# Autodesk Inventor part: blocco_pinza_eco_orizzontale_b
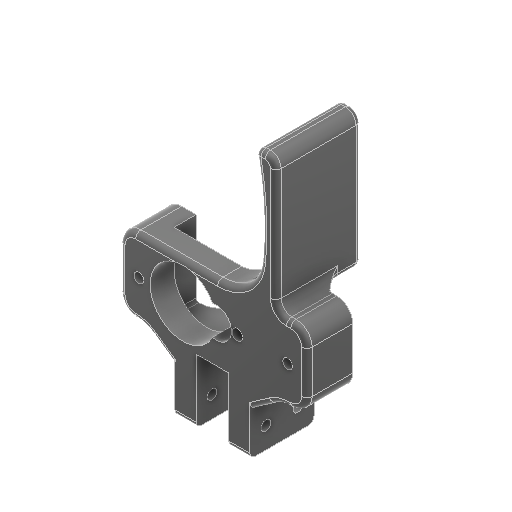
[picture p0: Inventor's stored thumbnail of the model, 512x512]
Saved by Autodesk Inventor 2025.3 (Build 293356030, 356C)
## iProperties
Created: 2026-03
Part Number: blocco_pinza_eco_orizzontale_b
Material: Plastica ABS
Document SubType Name: Modeling
Designer: Ryzen5700u
Density: 1.06 g/cm^3
Appearance: Liscia - Nero
Author: Ryzen5700u
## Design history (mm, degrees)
sketch "Schizzo1"
  geometry: L1 (11.4, -6)-(11.4, 6) reference; L2 (17.5, -7)-(-17.5, -7); L3 (-17.5, -7)-(-17.5, 7); L4 (-17.5, 7)-(17.5, 7); L5 (17.5, 7)-(17.5, -7); A1 r 2.7 centre (0.55, 0) between (-0.234, -2.584) and (-0.234, 2.584) reference; A2 r 6 centre (-5.65, 0) between (-0.234, 2.584) and (-0.234, -2.584) reference; A3 r 2.85 centre (0.55, 0) between (-0.155, -2.762) and (-0.155, 2.762); A4 r 6.15 centre (-5.65, 0) between (-0.155, 2.762) and (-0.155, -2.762); 1 further point
  constraints: 8 end point, 8 point on circle, 4 centre point, 2 parallel, 1 horizontal, 1 perpendicular, 7 other
  dimensions: "d1" = 35 distance of L3.end L4.end; "d2" = 14 distance of L2.end L3.end; "d66" = 0.15 radial gap between concentric circles of A2 A4
extrude "Estrusione1" new body sketch "Schizzo1" distance "d4" = 4.5; taper "d5" = 0 deg
sketch "Schizzo3"
  geometry: L1 (-17.5, 7)-(17.5, 7) reference; L2 (-17.5, -7)-(-17.5, 7) reference; L3 (17.5, -7)-(-17.5, -7) reference; L4 (17.5, 7)-(17.5, -7) reference; L5 (-11.7, 7)-(-11.7, -7); L6 (11.8, 7)-(11.8, -7); 1 further point
  constraints: 4 end point, 4 point on line, 2 perpendicular
  dimensions: "d13" = 5.8 distance between parallel lines of L2 L5; "d14" = 5.7 distance between parallel lines of L4 L6
  node "Linea chiusa proiettata1"
node "Piano di lavoro1"
extrude "Estrusione2" join sketch "Schizzo3" distance "d15" = 4.1; taper "d16" = 0 deg
fillet "Raccordo1" dims "d17" = 3
sketch "Schizzo4"
  geometry: L1 (11, -7)-(11, 33); L2 (17.5, -4)-(17.5, 4) reference; L3 (7, -7)-(7, 33); L4 (11, 33)-(7, 33); L5 (-14.5, -7)-(14.5, -7) reference; 1 further point
  constraints: 6 end point, 1 horizontal, 1 parallel, 1 point on line, 1 vertical
  dimensions: "d18" = 40 distance of L1.start L1.end; "d19" = 6.5 distance between parallel lines of L2 L1; "d20" = 4 distance between parallel lines of L1 L3
extrude "Estrusione3" join sketch "Schizzo4" distance "d21" = 10; taper "d22" = 0 deg
chamfer "Smusso1" distance "d23" = 5; stored, may be unused: second distance "d24" = 2, angle "d25" = 45 deg
chamfer "Smusso2" distance "d26" = 5; stored, may be unused: second distance "d27" = 2, angle "d28" = 45 deg
sketch "Schizzo5"
  geometry: L1 (11.8, 0)-(11.65, -25.421) reference; L2 (14.65, 4.5)-(8.65, 4.5); L3 (8.65, 4.5)-(8.65, -7.5); L4 (8.65, -7.5)-(14.65, -7.5); L5 (14.65, -7.5)-(14.65, 4.5); L6 (14.65, 4.5)-(18.65, 4.5); L7 (18.65, 4.5)-(18.65, -7.5); L8 (18.65, -7.5)-(14.65, -7.5); L9 (14.65, -7.5)-(14.65, 4.5); L10 (8.65, 4.5)-(4.65, 4.5); L11 (4.65, 4.5)-(4.65, -7.5); L12 (4.65, -7.5)-(8.65, -7.5); L13 (8.65, -7.5)-(8.65, 4.5); 4 further points
  constraints: 26 end point, 6 parallel, 3 horizontal, 3 perpendicular, 3 point on line, 2 vertical, 1 other
  dimensions: "d29" = 6 distance of L4.end L3.end; "d30" = 12 distance of L3.end L2.end; "d31" = 4 distance of L7.end L8.end; "d32" = 4 distance of L12.end L11.end
extrude "Estrusione4" join sketch "Schizzo5" distance "d33" = 12; taper "d34" = 0 deg
sketch "Schizzo6"
  geometry: C1 r 2.45 at (6, -6) reference; 1 further point
hole "Foro2" sketch "Schizzo6" at (6, -6) diameter "d41" = 3.2; stored, may be unused: countersink angle "d45" = 90 deg, drill point angle "d47" = 118 deg; dims "d42" = 6, "d43" = 6.5, "d44" = 3.4, "d46" = 8
chamfer "Smusso5" distance "d48" = 2.7; stored, may be unused: second distance "d49" = 2, angle "d50" = 45 deg
fillet "Raccordo2" dims "d51" = 3
sketch "Schizzo7"
  geometry: L1 (0, 4.5)-(0, 0) reference; L2 (0, 0)-(6, 0) reference; L3 (6, 0)-(6, 4.5) reference; L4 (0, 4.5)-(6, 4.5) reference; 1 further point
extrude "Estrusione5" join sketch "Schizzo7" stored distance "d52" = 10; taper "d53" = 0 deg
sketch "Schizzo8"
  geometry: L1 (-7.15, -19)-(-3.15, -19) reference; L2 (-7.15, -19)-(6.85, -19); L3 (6.85, -19)-(6.85, -14); L4 (6.85, -14)-(-7.15, -14); L5 (-7.15, -14)-(-7.15, -19); 7 further points
  constraints: 8 end point, 2 parallel, 1 horizontal, 1 perpendicular, 2 other
  dimensions: "d63" = 5 distance of L3.end L2.end
extrude "Estrusione6" cut sketch "Schizzo8" distance "d64" = 15; taper "d65" = 0 deg
sketch "Schizzo10"
  geometry: A1 r 1 centre (13.9, 0) between (14.7, 0.6) and (14.7, -0.6) reference; A2 r 1 centre (-13.9, 0) between (-14.7, -0.6) and (-14.7, 0.6) reference; 1 further point
  constraints: 4 point on circle, 2 centre point, 8 other
hole "Foro3" sketch "Schizzo10" at (13.9, 0), (-13.9, 0) diameter "d67" = 1.8; stored, may be unused: countersink angle "d71" = 90 deg, drill point angle "d73" = 118 deg; dims "d68" = 6, "d69" = 3.5, "d70" = 1.8, "d72" = 8
chamfer "Smusso9" distance "d74" = 4; stored, may be unused: second distance "d75" = 2, angle "d76" = 45 deg
sketch "Schizzo11"
  geometry: L1 (10, 5)-(1.15, -3.85) reference; L2 (10, 40)-(10, 5) reference; L3 (0, 40)-(10, 40) reference; L4 (0, 40)-(0, 14) reference; L5 (0, -3.85)-(0, 14) reference; L6 (0, -3.85)-(1.15, -3.85) reference; 1 further point
extrude "Estrusione7" cut sketch "Schizzo11" extent not by distance; stored distance "d77" = 0; taper "d78" = 0 deg
fillet "Raccordo3" dims "d79" = 1
sketch "Schizzo12"
  geometry: C1 r 1 at (4.5, 0) reference; 1 further point
hole "Foro4" sketch "Schizzo12" at (4.5, 0) diameter "d80" = 2; stored, may be unused: countersink angle "d84" = 90 deg, drill point angle "d86" = 118 deg; dims "d81" = 6, "d82" = 3.5, "d83" = 1.8, "d85" = 8
sketch "Schizzo13"
  geometry: L1 (4, -11)-(0, -11) reference; L2 (4, 0)-(4, -11) reference; L3 (4, 0)-(0, 0) reference; L4 (0, 0)-(0, -11) reference; L5 (14, -11)-(10, -11) reference; L6 (14, 0)-(14, -11) reference; L7 (14, 0)-(10, 0) reference; L8 (10, 0)-(10, -11) reference; L9 (10, 0)-(4, 0) reference; L10 (3.95, 14.018)-(10.05, 14.018); L11 (10.05, 14.018)-(10.05, -14.018); L12 (10.05, -14.018)-(3.95, -14.018); L13 (3.95, -14.018)-(3.95, 14.018); L14 (3.95, 14.018)-(10.05, -14.018); L15 (10.05, 14.018)-(3.95, -14.018); 6 further points
  constraints: 12 end point, 3 midpoint, 2 parallel, 1 horizontal, 1 perpendicular
  dimensions: "d87" = 6.1 distance of L11.end L12.end
extrude "Estrusione8" cut sketch "Schizzo13" extent not by distance; stored distance "d88" = 0; taper "d89" = 0 deg
sketch "Schizzo15"
  geometry: L1 (11.7, 7)-(11.7, -7) reference; L2 (11.7, 7)-(7.7, 7); L3 (7.7, 7)-(7.7, 32); L4 (7.7, 32)-(11.7, 32); L5 (11.7, 32)-(11.7, 7); L6 (11.7, 7)-(-11.8, 7) reference; L7 (7.7, 7)-(11.7, 7); L8 (11.7, 7)-(11.7, 6.8); L9 (11.7, 6.8)-(7.7, 6.8); L10 (7.7, 6.8)-(7.7, 7); 2 further points
  constraints: 16 end point, 4 parallel, 2 horizontal, 2 perpendicular, 1 point on line
  dimensions: "d90" = 4 distance of L3.end L4.end; "d91" = 25 distance of L2.end L3.end; "d94" = 0.2 distance of L7.end L8.end
extrude "Estrusione9" join sketch "Schizzo15" distance "d92" = 16; taper "d93" = 0 deg
fillet "Raccordo4" dims "d95" = 2
sketch "Schizzo16"
  geometry: L1 (-11.7, 32)-(-7.7, 32) reference; L2 (-7.7, 32)-(-7.7, 7) reference; A1 r 60 centre (50.983, 19.5) between (-7.7, 32) and (-7.7, 7); 1 further point
  constraints: 2 point on circle, 1 centre point
  dimensions: "d96" = 60 radius of A1
extrude "Estrusione10" cut sketch "Schizzo16" extent not by distance; stored distance "d97" = 0; taper "d98" = 0 deg
fillet "Raccordo5" dims "d99" = 2
fillet "Raccordo6" dims "d100" = 1
fillet "Raccordo7" dims "d101" = 3
fillet "Raccordo8" dims "d102" = 1
fillet "Raccordo9" dims "d103" = 8
fillet "Raccordo10" dims "d104" = 5
sketch "Schizzo17"
  geometry: L1 (0, 0)-(0, 6.922) reference; L2 (0, 0)-(0, -0.155) reference; L3 (0, -7.078)-(0, -0.155) reference; L4 (4.1, 6.922)-(4.1, -7.078) reference; L5 (0, 6.922)-(4.1, 6.922) reference; L6 (0, 6.022)-(0, -6.178) reference; L7 (4.1, -7.078)-(-4.5, -7.078) reference; L8 (0, -7.078)-(4.1, -7.078); L9 (0, -7.078)-(4.1, -7.078) reference; L10 (0, 6.022)-(3.8, 6.022) reference; L11 (3.8, 6.022)-(3.8, -6.178) reference; L12 (3.8, -6.178)-(0, -6.178) reference; 6 further points
  constraints: 2 end point, 2 point on line, 1 collinear
extrude "Estrusione11" join sketch "Schizzo17" stored distance "d105" = 10; taper "d106" = 0 deg
sketch "Schizzo18"
  geometry: L1 (7.15, -11)-(7.15, -7) reference; L2 (7.15, -11)-(11.15, -7) reference; L3 (11.8, -7)-(11.15, -7) reference; L4 (-7.7, 10.915)-(-7.7, 6.8) reference; L5 (-7.7, 6.8)-(-11.7, 6.8) reference; L6 (-11.7, 6.8)-(-11.7, -7) reference; L7 (-6.85, -11)-(-10.85, -7) reference; L8 (-6.85, -7)-(-6.85, -11) reference; L9 (-2.9, -7)-(-6.85, -7) reference; L10 (3.2, -7)-(-2.9, -7) reference; L11 (7.15, -7)-(3.2, -7) reference; L12 (-0.821, 7)-(11.8, 7) reference; L13 (-10.85, -7)-(-11.7, -7) reference; L14 (11.8, -7)-(11.8, -0.078) reference; L15 (11.8, 0.078)-(11.8, 7) reference; A1 r 6.15 centre (5.65, 0) between (0.155, -2.762) and (11.8, -0.078) reference; A2 r 2.85 centre (-0.55, 0) between (0.155, 2.762) and (0.155, -2.762) reference; A3 r 6.15 centre (5.65, 0) between (11.8, 0.078) and (0.155, 2.762) reference; A4 r 8 centre (-0.821, 15) between (-7.7, 10.915) and (-0.821, 7) reference; 1 further point
extrude "Estrusione12" join sketch "Schizzo18" stored distance "d107" = 10; taper "d108" = 0 deg
sketch "Schizzo19"
  geometry: L1 (4.1, 12.95)-(0, 12.95) reference; L2 (0, -0.85)-(0, 12.95) reference; L3 (4.1, 12.95)-(4.1, -0.85) reference; L4 (-3.4, -0.85)-(4.1, -0.85) reference; L5 (4.1, -0.85)-(0, -0.85) reference; 2 further points
extrude "Estrusione13" join sketch "Schizzo19" stored distance "d109" = 10; taper "d110" = 0 deg
sketch "Schizzo20"
  geometry: L1 (-6.85, -11)-(-10.85, -7) reference; L2 (-6.85, -7)-(-6.85, -11) reference; L3 (-10.85, -7)-(-11.7, -7) reference; L4 (-7.7, 10.915)-(-7.7, 6.8) reference; L5 (-7.7, 6.8)-(-11.7, 6.8) reference; L6 (-11.7, 6.8)-(-11.7, -7) reference; L7 (-2.9, -7)-(-6.85, -7) reference; L8 (3.2, -7)-(-2.9, -7) reference; L9 (7.15, -7)-(3.2, -7) reference; L10 (7.15, -11)-(7.15, -7) reference; L11 (7.15, -11)-(11.15, -7) reference; L12 (11.8, -7)-(11.15, -7) reference; L13 (11.8, -7)-(11.8, -0.078) reference; L14 (11.8, 0.078)-(11.8, 7) reference; L15 (-0.821, 7)-(11.8, 7) reference; L16 (-7.7, 10.915)-(-7.7, 6.8) reference; L17 (-7.7, 6.8)-(-11.7, 6.8) reference; L18 (-11.7, 6.8)-(-11.7, -7) reference; L19 (-10.85, -7)-(-11.7, -7) reference; L20 (-6.85, -11)-(-10.85, -7) reference; L21 (-6.85, -7)-(-6.85, -11) reference; L22 (-2.9, -7)-(-6.85, -7) reference; L23 (3.2, -7)-(-2.9, -7) reference; L24 (7.15, -7)-(3.2, -7) reference; L25 (7.15, -11)-(7.15, -7) reference; L26 (7.15, -11)-(11.15, -7) reference; L27 (11.8, -7)-(11.15, -7) reference; L28 (11.8, -7)-(11.8, -0.078) reference; L29 (11.8, 0.078)-(11.8, 7) reference; L30 (-0.821, 7)-(11.8, 7) reference; L31 (7.15, -7)-(11.15, -7); L32 (-6.85, -7)-(-10.85, -7); L33 (7.15, -11)-(12.863, -7); L34 (7.15, -11)-(13.979, -11); L35 (11.8, -7)-(14.5, -7) reference; L36 (-14.5, -7)-(-11.7, -7) reference; L37 (-6.85, -11)-(-12.842, -6.804); L38 (-6.85, -11)-(0.465, -11); C1 r 1 at (-4.5, 0) reference; A1 r 6.15 centre (5.65, 0) between (0.155, -2.762) and (11.8, -0.078) reference; A2 r 2.85 centre (-0.55, 0) between (0.155, 2.762) and (0.155, -2.762) reference; A3 r 6.15 centre (5.65, 0) between (11.8, 0.078) and (0.155, 2.762) reference; A4 r 8 centre (-0.821, 15) between (-7.7, 10.915) and (-0.821, 7) reference; A5 r 6.15 centre (5.65, 0) between (0.155, -2.762) and (11.8, -0.078) reference; A6 r 2.85 centre (-0.55, 0) between (0.155, 2.762) and (0.155, -2.762) reference; A7 r 6.15 centre (5.65, 0) between (11.8, 0.078) and (0.155, 2.762) reference; A8 r 8 centre (-0.821, 15) between (-7.7, 10.915) and (-0.821, 7) reference; 8 further points
  constraints: 12 end point, 2 collinear, 2 horizontal, 1 equal length, 1 point on line
  dimensions: "d132" = 35 deg angle of L34 L33; "d133" = 145 deg angle of L38 L37
extrude "Estrusione14" join sketch "Schizzo20" stored distance "d111" = 10; taper "d112" = 0 deg
fillet "Raccordo11" dims "d123" = 1
fillet "Raccordo12" dims "d124" = 1.9
sketch "Schizzo23"
  geometry: L1 (0.821, 7)-(-14.5, 7) reference; L2 (-17.5, 4)-(-17.5, -4) reference; L3 (-14.5, -7)-(-11.15, -7) reference; L4 (-7.15, -11)-(-11.15, -7) reference; L5 (-7.15, -11)-(-7.15, -18) reference; L6 (-3.2, -18)-(-7.15, -18) reference; L7 (-3.2, -18)-(-3.2, -7) reference; L8 (-3.2, -7)-(2.9, -7) reference; L9 (2.9, -7)-(2.9, -18) reference; L10 (6.85, -18)-(2.9, -18) reference; L11 (6.85, -11)-(6.85, -18) reference; L12 (10.85, -7)-(6.85, -11) reference; L13 (10.85, -7)-(14.5, -7) reference; L14 (17.5, -4)-(17.5, 4) reference; L15 (14.5, 7)-(13.7, 7) reference; L16 (11.7, 9)-(11.7, 30) reference; L17 (9.7, 32)-(8.923, 32) reference; L18 (-7.15, -11)-(-11.8, -7); L19 (-7.15, -11)-(-12.089, -7); C1 r 1 at (4.5, 0) reference; C2 r 0.9 at (-13.9, 0) reference; C3 r 0.9 at (13.9, 0) reference; A1 r 6.15 centre (-5.65, 0) between (-0.155, 2.762) and (-0.155, -2.762) reference; A2 r 2.85 centre (0.55, 0) between (-0.155, -2.762) and (-0.155, 2.762) reference; A3 r 1 centre (8.923, 31) between (8.923, 32) and (7.941, 30.811) reference; A4 r 60 centre (-50.983, 19.5) between (8.791, 14.308) and (7.941, 30.811) reference; A5 r 8 centre (0.821, 15) between (0.821, 7) and (8.791, 14.308) reference; A6 r 3 centre (-14.5, 4) between (-14.5, 7) and (-17.5, 4) reference; A7 r 3 centre (-14.5, -4) between (-17.5, -4) and (-14.5, -7) reference; A8 r 3 centre (14.5, -4) between (14.5, -7) and (17.5, -4) reference; A9 r 3 centre (14.5, 4) between (17.5, 4) and (14.5, 7) reference; A10 r 2 centre (13.7, 9) between (11.7, 9) and (13.7, 7) reference; A11 r 2 centre (9.7, 30) between (11.7, 30) and (9.7, 32) reference; 1 further point
  constraints: 4 end point, 1 point on line
extrude "Estrusione16" join sketch "Schizzo23" stored distance "d127" = 10; taper "d128" = 0 deg
sketch "Schizzo24"
  geometry: L1 (11.8, -7)-(3.2, -7) reference; L2 (3.2, -7)-(-2.9, -7) reference; L3 (-10.85, -7)-(-11.7, -7) reference; L4 (-2.9, -7)-(-10.85, -7) reference; L5 (11.8, -7)-(11.8, -0.078) reference; L6 (11.8, 0.078)-(11.8, 7) reference; L7 (-0.821, 7)-(11.8, 7) reference; L8 (7.15, -7)-(11.15, -7); L9 (-7.7, 6.8)-(-11.7, 6.8) reference; L10 (-11.7, 6.8)-(-11.7, -7) reference; L11 (-7.7, 10.915)-(-7.7, 6.8) reference; C1 r 1 at (-4.5, 0) reference; A1 r 6.15 centre (5.65, 0) between (0.155, -2.762) and (11.8, -0.078) reference; A2 r 2.85 centre (-0.55, 0) between (0.155, 2.762) and (0.155, -2.762) reference; A3 r 6.15 centre (5.65, 0) between (11.8, 0.078) and (0.155, 2.762) reference; A4 r 8 centre (-0.821, 15) between (-7.7, 10.915) and (-0.821, 7) reference; 1 further point
  constraints: 2 end point, 1 horizontal
extrude "Estrusione17" join sketch "Schizzo24" stored distance "d129" = 10; taper "d130" = 0 deg
sketch "Schizzo25"
  geometry: L1 (6.85, -11)-(10.85, -7) reference; L2 (12.563, -7)-(6.85, -11) reference; L3 (11.7, -7)-(12.563, -7) reference; L4 (10.85, -7)-(11.7, -7) reference; L5 (-7.15, -11)-(-12.863, -7) reference; L6 (-7.15, -11)-(-12.089, -7) reference; L7 (-12.863, -7)-(-12.089, -7) reference; L8 (-7.15, -11)-(-12.863, -7) reference; 3 further points
extrude "Estrusione18" join sketch "Schizzo25" stored distance "d134" = 10; taper "d135" = 0 deg
fillet "Raccordo14" dims "d136" = 4
fillet "Raccordo15" dims "d137" = 6
fillet "Raccordo16" dims "d138" = 1
sketch "Schizzo26"
  geometry: C1 r 0.9 at (2, 4) reference; C2 r 0.9 at (8, 4) reference; 1 further point
hole "Foro6" sketch "Schizzo26" at (2, 4), (8, 4) diameter "d139" = 1.8; stored, may be unused: countersink angle "d143" = 90 deg, drill point angle "d145" = 118 deg; dims "d140" = 6, "d141" = 3.5, "d142" = 1.8, "d144" = 8
fillet "Raccordo17" dims "d146" = 0.5
fillet "Raccordo18" dims "d147" = 7
fillet "Raccordo19" dims "d148" = 0.5
fillet "Raccordo20" dims "d149" = 1
node "Solido1"
node "Riferimento4"
node "Linea chiusa proiettata2"
node "Linea chiusa proiettata3"
node "Riferimento5"
node "Linea chiusa proiettata4"
node "Linea chiusa proiettata5"
node "Linea chiusa proiettata6"
node "Riferimento13"
node "Linea chiusa proiettata7"
node "Linea chiusa proiettata8"
node "Linea chiusa proiettata9"
node "Linea chiusa proiettata12"
node "Linea chiusa proiettata13"
node "Linea chiusa proiettata14"
node "Linea chiusa proiettata15"
node "Linea chiusa proiettata16"
node "Riferimento14"
node "Riferimento15"
